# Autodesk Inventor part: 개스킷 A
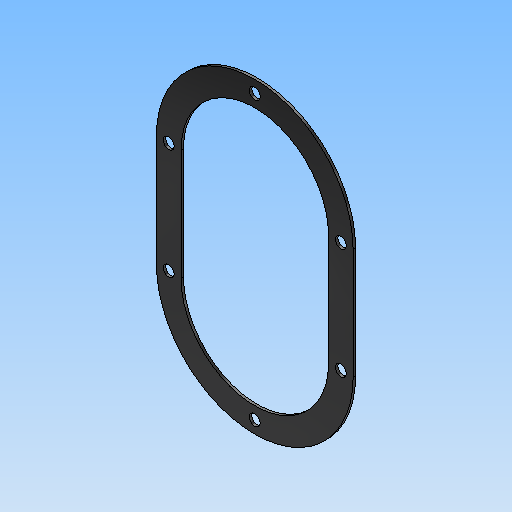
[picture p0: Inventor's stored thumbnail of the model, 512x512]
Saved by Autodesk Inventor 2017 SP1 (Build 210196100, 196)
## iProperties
Created: 2020-04
Part Number: 개스킷 A
Material: 고무
Document SubType Name: Modeling
Designer: mduedu
Density: 0.93 g/cm^3
Mass: 2.61813 g
Surface Area: 62.9733 cm^2
Volume: 2.81519 cm^3
Appearance: 고무 - 검은색 - 버전 1.1
Author: mduedu
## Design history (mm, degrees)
sketch "스케치1"
  geometry: L1 (-40, 0)-(-40, -45); L2 (40, 0)-(40, -45); A1 r 40 centre (0, 0) between (40, 0) and (-40, 0); A2 r 40 centre (0, -45) between (-40, -45) and (40, -45); 1 further point
  constraints: 4 end point, 4 point on circle, 4 tangent, 2 centre point, 1 coincident, 1 equal radius, 1 vertical alignment
  dimensions: "d0" = 80 diameter of A1; "d21" = 45 distance of point (0, 0) A2.centre
extrude "돌출1" new body sketch "스케치1" distance "d1" = 1; taper "d2" = 0 deg
sketch "스케치4"
  geometry: L1 (-30, 0)-(-30, -45); L2 (30, 0)-(30, -45); A1 r 30 centre (0, 0) between (30, 0) and (-30, 0); A2 r 30 centre (0, -45) between (-30, -45) and (30, -45); 1 further point
  constraints: 4 end point, 4 point on circle, 4 tangent, 2 centre point, 1 coincident, 1 equal radius, 1 vertical alignment
  dimensions: "d17" = 60 diameter of A1; "d24" = 45 distance of point (0, 0) A2.centre
extrude "돌출3" cut sketch "스케치4" stored distance "d18" = 1; taper "d19" = 0 deg
sketch "스케치3"
  geometry: A1 r 35 centre (0, 0) between (0, 35) and (-35, 0); A2 r 35 centre (0, -45) between (-35, -45) and (0, -80); 3 further points
  constraints: 6 point on circle, 5 vertical alignment, 3 horizontal alignment, 2 centre point, 1 coincident, 1 equal radius
  dimensions: "d6" = 70 diameter of A1; "d28" = 45 distance of point (0, 0) A2.centre
hole "구멍1" sketch "스케치3" at (0, 35), (-35, 0), (35, 0), (35, -45), (-35, -45), (0, -80) diameter "d7" = 4.5; stored, may be unused: countersink angle "d11" = 90 deg, drill point angle "d13" = 118 deg; dims "d8" = 6, "d9" = 4, "d10" = 2, "d12" = 8
node "솔리드1"
